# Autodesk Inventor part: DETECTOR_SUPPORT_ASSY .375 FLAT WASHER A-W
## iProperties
Shininess: 64.0
Length Units: 11272
Angle Units: 11279
Time Units: 11290
Mass Units: 11286
Length Display Precision: 3
Angle Display Precision: 2
Compacted: True
Part Number: DETECTOR_SUPPORT_ASSY .375 FLAT WASHER A-W
Document SubType Name: Modeling
Created: 2004-08
Designer: John Blackburn
Material: STAINLESS_STEEL, AUSTENITIC
Manufacturer: Standard
Standards Organization: Custom
Density: 0.0
Volumn: 0.0
Area: 0.0
PropertySet Name: Model Information
Control State: 0
Master: False
Checked Out: False
Author: John Blackburn
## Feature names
1. Base1
